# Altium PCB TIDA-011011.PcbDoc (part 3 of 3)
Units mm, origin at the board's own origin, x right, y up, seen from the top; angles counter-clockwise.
Board outline 61 x 47.5 mm, 4 copper layers (Top Layer, Layer 1, Layer 2, Bottom Layer), stack 1.787 mm thick; 171 components, 73 nets, 455 pads, 298 vias.
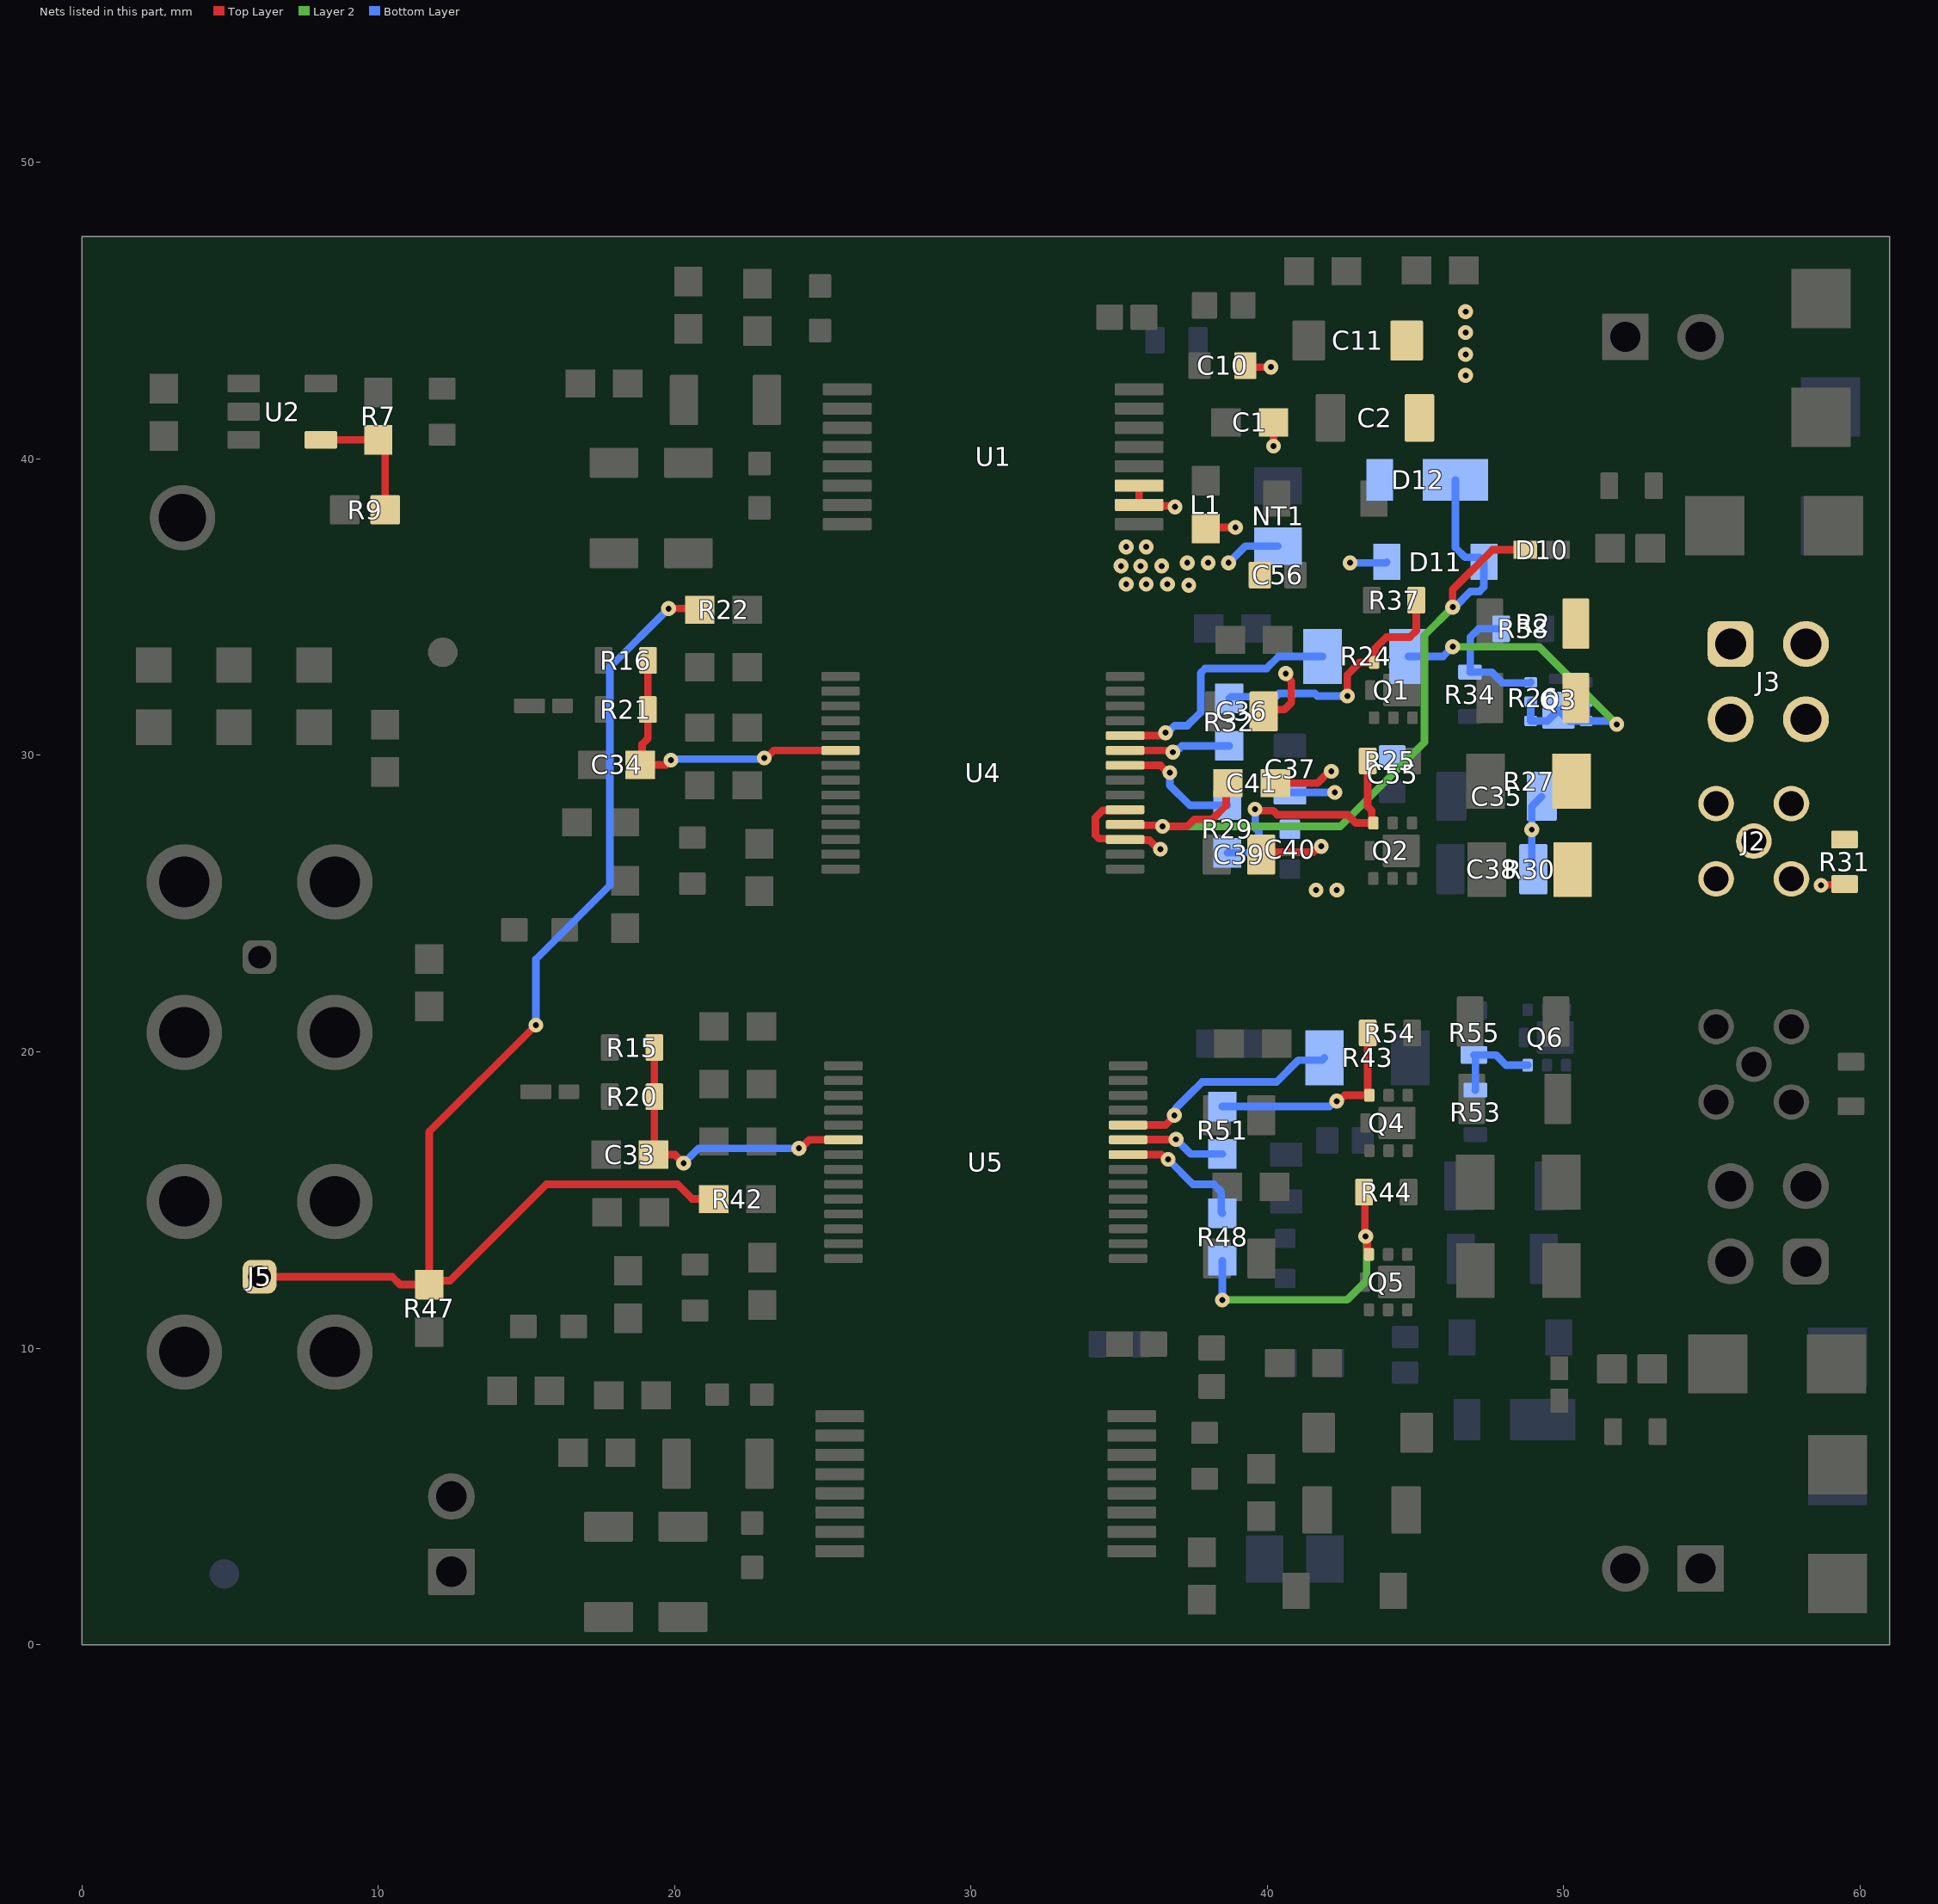
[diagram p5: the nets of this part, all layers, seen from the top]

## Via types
v1: diameter 0.5, hole 0.2, Top Layer to Bottom Layer, tented both sides, 298 vias

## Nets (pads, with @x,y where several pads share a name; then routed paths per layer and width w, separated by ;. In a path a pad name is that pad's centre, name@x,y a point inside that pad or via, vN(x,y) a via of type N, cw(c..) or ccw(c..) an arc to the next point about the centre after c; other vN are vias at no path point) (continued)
NetQ1_3: Q1.3 R32.2 R37.2 | length 9
  Top Layer w0.254: v1(42.698,32.002) 42.698,32.715 43.119,33.136 Q1.3@43.6,33.136 43.632,33.169 43.632,33.603 44.017,33.987 44.809,33.987 45.025,34.203 R37.2@45.025,35.235
  Bottom Layer w0.254: R32.2@38.712,31.921 38.769,31.978 40.289,31.978 40.397,32.086 41.607,32.086 41.691,32.002 v1(42.698,32.002)
NetQ2_3: Q2.3 R25.1 R29.2 | length 8.8
  Top Layer w0.254: v1(39.58,28.183) 39.627,28.136 40.198,28.136 40.338,27.996 42.708,27.996 42.986,27.718 43.521,27.718 43.525,27.722 43.525,28.135 43.388,28.272 R25.1@43.388,29.816
  Bottom Layer w0.254: R29.2@38.649,26.716 39.567,26.716 39.716,26.864 39.716,27.425 39.589,27.552 39.589,28.175 v1(39.58,28.183)
NetQ3_3: Q3.3 R34.2 R38.2 | length 4.5
  Bottom Layer w0.254: R38.2@47.887,34.272 47.129,34.272 46.845,33.987 46.845,32.818 R34.2@46.837,32.809 47.575,32.809 47.94,32.444 48.866,32.444 Q3.3@48.885,32.463
NetQ4_3: Q4.3 R51.2 R54.2 | length 7.2
  Top Layer w0.254: v1(42.342,18.338) 42.408,18.338 42.607,18.536 Q4.3@43.439,18.536 43.439,18.576 43.388,18.628 R54.2@43.388,20.634
  Bottom Layer w0.254: R51.2@38.484,18.156 42.094,18.156 42.275,18.338 v1(42.342,18.338)
NetQ5_3: Q5.3 R44.1 R48.2 | length 10.1
  Top Layer w0.254: R44.1@43.264,15.268 43.291,15.241 43.291,13.806 v1(43.318,13.778) 43.318,13.713 43.376,13.655 43.376,13.217 Q5.3@43.424,13.169
  Layer 2 w0.254: v1(38.484,11.633) 42.697,11.633 43.352,12.288 43.352,13.744 v1(43.318,13.778)
  Bottom Layer w0.254: v1(38.484,11.633) R48.2@38.484,12.951
NetQ6_3: Q6.3 R53.2 R55.2 | length 3.2
  Bottom Layer w0.254: R53.2@47.011,18.7 R53.2@47.022,18.711 47.022,19.844 R55.2@46.972,19.894 47.714,19.894 48.059,19.548 Q6.3@48.78,19.548
NetR7_1: R7.1 R9.2 U2.4 | length 4.6
  Top Layer w0.254: U2.4@8.063,40.643 10.164,40.643 R7.1@10.234,40.712 ; R9.2@10.234,38.284 R7.1@10.234,40.712 ; R7.1@10.247,40.725 R7.1@10.234,40.712
NetR24_1: R24.1 U4.24 | length 8.5
  Top Layer w0.254: U4.24@35.2,30.666 36.401,30.666 36.498,30.763 v1(36.564,30.763)
  Bottom Layer w0.254: v1(36.564,30.763) 36.631,30.763 36.872,31.003 37.303,31.003 37.752,31.453 37.752,32.781 37.901,32.929 39.973,32.929 40.382,33.338 R24.1@41.864,33.338
NetR43_1: R43.1 U5.24 | length 7.7
  Top Layer w0.254: U5.24@35.3,17.532 36.564,17.532 36.863,17.83 v1(36.863,17.86)
  Bottom Layer w0.254: v1(36.863,17.86) 36.91,17.907 36.91,18.094 37.354,18.539 37.798,18.983 40.307,18.983 41.043,19.718 41.844,19.718 R43.1@41.925,19.799
OUTN_BOT: R51.1 U5.23 | length 3.4
  Top Layer w0.254: U5.23@35.3,17.032 35.308,17.04 36.91,17.04 v1(36.918,17.049)
  Bottom Layer w0.254: v1(36.918,17.049) 37.411,16.556 R51.1@38.484,16.556
OUTN_TOP: R32.1 U4.23 | length 3.6
  Top Layer w0.254: U4.23@35.2,30.166 36.687,30.166 36.745,30.108 v1(36.811,30.108)
  Bottom Layer w0.254: v1(36.811,30.108) 36.876,30.108 37.001,30.233 37.031,30.233 37.119,30.321 R32.1@38.712,30.321
OUTP_BOT: R48.1 U5.22 | length 4.4
  Top Layer w0.254: U5.22@35.3,16.532 36.425,16.532 36.584,16.373 v1(36.651,16.373)
  Bottom Layer w0.254: v1(36.651,16.373) 37.491,15.532 38.191,15.532 38.448,15.274 38.448,14.587 R48.1@38.484,14.551
OUTP_TOP: R29.1 U4.22 | length 4.3
  Top Layer w0.254: U4.22@35.2,29.666 36.392,29.666 36.643,29.415 v1(36.71,29.415)
  Bottom Layer w0.254: v1(36.71,29.415) 36.707,29.413 36.707,28.995 37.387,28.316 R29.1@38.649,28.316
RDY_BOT: C33.1 R15.1 R20.2 U5.6 | length 10.5
  Top Layer w0.254: C33.1@19.295,16.532 19.319,16.556 R20.2@19.319,18.486 R15.1@19.319,20.144 ; C33.1@19.296,16.531 20.019,16.531 v1(20.306,16.244) ; v1(24.196,16.746) 24.262,16.746 24.548,17.032 U5.6@25.7,17.032
  Bottom Layer w0.254: v1(20.306,16.244) 20.808,16.746 v1(24.196,16.746)
RDY_TOP: C34.1 R16.1 R21.2 U4.6 | length 10.6
  Top Layer w0.254: C34.1@18.845,29.683 18.908,29.746 18.908,30.374 19.104,30.569 R16.1@19.104,33.204 ; C34.1@18.846,29.682 19.717,29.682 v1(19.876,29.841) ; v1(23.027,29.915) 23.094,29.915 23.344,30.166 U4.6@25.6,30.166
  Bottom Layer w0.254: v1(19.876,29.841) 19.913,29.878 22.99,29.878 v1(23.027,29.915)
TOP-PWM: J5.1 R22.1 R42.1 R47.2 | length 44.3
  Top Layer w0.254: J5.1@6,12.415 10.474,12.415 10.741,12.148 R47.2@11.721,12.148 ; v1(15.321,20.901) 11.721,17.3 R47.2@11.721,12.148 ; v1(19.797,34.951) 20.813,34.951 R22.1@20.85,34.915 ; R42.1@21.325,15.032 21.315,15.041 20.592,15.041 20.102,15.532 15.679,15.532 12.428,12.281 11.853,12.281 R47.2@11.721,12.148
  Bottom Layer w0.254: v1(15.321,20.901) 15.321,23.121 17.819,25.619 17.819,32.974 v1(19.797,34.951)
TOP_Gate: J2.1 J3.2 J3.4 Q3.1 Q3.2 Q3.5 Q3.6 Q3.7 R2.2 R24.2 R26.2 R27.2 R30.2 R31.2 | length 13.2
  Top Layer w0.254: J3.2@55.83,30.867 J3.2@55.83,31.217 ; J2.1@56.411,27.106 J2.1@56.438,27.133 ; R31.2@59.445,27.133 R31.2@59.472,27.159
  Layer 2 w0.254: v1(46.253,33.666) 49.169,33.666 v1(51.787,31.048)
  Bottom Layer w0.254: R24.2@44.764,33.338 45.926,33.338 v1(46.253,33.666) ; Q3.2@48.885,31.813 Q3.1@48.885,31.163 49.455,31.163 Q3.7@49.82,31.528 50.185,31.163 Q3.6@50.755,31.163 ; Q3.5@50.755,31.813 Q3.6@50.755,31.163 ; v1(51.787,31.048) 51.72,31.048 51.605,31.163 Q3.6@50.755,31.163
TOP_OC: C41.1 D10.1 D11.1 D12.1 U4.18 | length 28.7
  Top Layer w0.254: U4.18@35.2,27.666 35.223,27.643 36.425,27.643 v1(36.462,27.606) 37.301,27.606 37.541,27.845 38.142,27.845 38.612,28.316 38.612,29.009 C41.1@38.669,29.066 ; v1(46.253,35) 46.253,35.592 47.597,36.935 D10.1@48.709,36.935
  Layer 2 w0.254: v1(36.462,27.606) 42.466,27.606 45.3,30.44 45.3,34.047 v1(46.253,35)
  Bottom Layer w0.254: v1(46.253,35) 46.32,35 46.849,35.529 47.155,35.529 47.304,35.678 D11.1@47.304,36.524 47.146,36.681 46.672,36.681 46.347,37.006 D12.1@46.347,39.293
TOP_Source: C1.2 C2.1 C10.2 C11.2 C35.1 C36.1 C37.1 C38.2 C39.2 C40.2 C41.2 C55.1 C56.2 D11.2 D12.2 J2.2 J2.3 J2.4 J2.5 J3.1 J3.3 L1.1 NT1.2 R31.1 U1.10 U1.11 U4.17 U4.19 | length 23.3
  Top Layer w0.254: U4.19@35.2,28.166 35.177,28.143 34.444,28.143 34.2,27.899 34.2,27.315 34.326,27.189 35.177,27.189 U4.17@35.2,27.166 35.223,27.143 36.017,27.143 36.321,26.839 v1(36.387,26.839) ; U1.11@35.675,39.099 U1.10@35.675,38.449 35.709,38.415 36.854,38.415 v1(36.888,38.381) ; L1.1@37.924,37.659 37.957,37.692 v1(38.923,37.692) ; C10.2@39.259,43.146 39.307,43.097 v1(40.118,43.097) ; C39.2@39.79,26.653 39.872,26.735 41.551,26.735 41.748,26.932 v1(41.814,26.932) ; C36.1@39.873,31.481 39.94,31.548 40.581,31.548 40.812,31.779 40.812,32.504 40.621,32.695 v1(40.621,32.761) ; v1(40.208,40.431) C1.2@40.208,41.231 ; C41.2@40.269,29.066 41.693,29.066 42.092,29.465 v1(42.158,29.465) ; J2.4@57.681,25.836 J2.4@57.77,25.748 ; v1(58.676,25.614) 58.698,25.637 59.449,25.637 R31.1@59.472,25.659
  Bottom Layer w0.254: v1(38.692,36.494) 39.255,37.057 NT1.2@40.362,37.057 ; C37.1@40.762,28.751 v1(42.275,28.751) ; v1(42.789,36.494) 44,36.494 D11.2@44.029,36.524 ; C38.2@48.973,26.158 48.92,26.212 v1(48.92,27.497) 48.922,27.5 48.922,28.283 C35.1@49.256,28.616 ; J3.1@55.749,33.676 J3.1@55.83,33.757
  other v1: 41.64,25.461 42.345,25.461 37.353,35.739 35.236,35.771 35.913,35.771 36.628,35.771 35.064,36.389 35.721,36.38 36.432,36.389 37.299,36.494 38.004,36.494 35.236,37.033 35.913,37.033 46.689,42.816 46.689,43.521 46.689,44.262 46.689,44.967
pads on no net: FID1.33 FID2.1 LBL1.0 U4.2 U4.3 U4.9 U4.12 U4.13 U4.16 U4.27 U5.2 U5.3 U5.9 U5.12 U5.13 U5.16 U5.27

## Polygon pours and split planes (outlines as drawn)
BOT_Source on Top Layer "TOP_LAYER_BOT_SOURCE_P028" (solid, pour order 28): 48.081,9.655 49.162,10.736 50.722,10.736 51.703,11.722 59.312,11.722 60.374,12.785 60.374,22.581 34.681,22.581 34.2,22.1 34.2,0.8 34.3,0.7 47.312,0.7 48.081,1.469
BOT_Gate on Top Layer "TOP_LAYER_BOT_GATE_P003" (solid, pour order 3): 49.035,21.79 49.035,11.443 49.01,11.418 49.042,11.385 50.797,11.385 50.797,13.664 51.159,14.026 59.212,14.026 59.212,16.473 58.477,17.207 56.8,17.207 56.647,17.361 56.647,18.214 57.654,19.221 60.042,19.221 60.226,19.405 60.226,20.605 50.431,20.605 50.431,21.908 49.035,21.908
TOP_Source on Top Layer "TOP_LAYER_TOP_SOURCE_P033" (solid, pour order 33): 34,46.841 47.853,46.841 48.318,46.376 48.318,37.797 51.152,34.964 59.454,34.964 60.374,34.044 60.374,25.19 60.274,25.089 34,25.089 34,46.798
GND on Top Layer "TOP_LAYER_GND_P025" (solid, pour order 25): 27.024,8.666 25.997,9.693 25.997,11.749 27.024,12.775 27.024,20.132 25.809,21.347 25.809,24.631 27.024,25.847 27.024,33.266 25.997,34.293 25.997,35.281 27.024,36.308 27.024,46.994 1.894,46.994 1,46.1 1,1.106 1.139,0.967 27,0.967 27.024,0.991
NetD13_2 on Top Layer "TOP_LAYER_NETD13_2_P034" (solid, pour order 34): 57.359,7.309 57.407,7.357 58.284,8.234 60.222,8.234 60.374,8.387 60.374,10.736 57.977,10.736 57.977,9.114 56.852,7.99 56.537,7.99 56.537,7.309
TOP_Gate on Top Layer "TOP_LAYER_TOP_GATE_P000" (solid, remove dead copper, pour order 0): 49.585,35.318 49.585,24.939 51.105,24.939 52.278,26.113 52.278,26.484 60.182,26.484 60.182,26.632 60.182,27.882 60.063,28.001 54.616,28.001 54,28.616 54,29.597 59.758,29.597 60.138,29.977 60.138,32.184 59.775,32.547 51.905,32.547 51.029,33.423 51.029,35.475 49.742,35.475
NetD19_2 on Top Layer "TOP_LAYER_NETD19_2_P031" (solid, pour order 31): 52.714,6.683 52.714,8.347 52.5,8.561 52.5,10.518 52.571,10.589 56.299,10.589 56.299,8.428 56.278,8.407 54.142,8.407 53.577,7.842 53.577,6.683
NetD13_1 on Top Layer "TOP_LAYER_NETD13_1_P024" (solid, pour order 24): 57.752,6.861 57.752,6.163 57.657,6.067 57.099,6.067 57.099,4.993 57.339,4.753 60.527,4.753 60.527,7.185 58.352,7.185 58.352,7.189 58.08,7.189
NetD14_1 on Top Layer "TOP_LAYER_NETD14_1_P021" (solid, pour order 21): 50.832,0.7 60.222,0.7 60.527,1.006 60.527,3.404 56.537,3.404 55.888,4.053 51.173,4.053 50.832,3.713
NetD8_2 on Top Layer "TOP_LAYER_NETD8_2_P011" (solid, pour order 11): 57.514,35.85 60.014,35.85 60.486,36.321 60.486,39.235 57.723,39.235 57.514,39.026
NetD18_2 on Top Layer "TOP_LAYER_NETD18_2_P016" (solid, pour order 16): 52.5,39.749 52.5,36.255 56.411,36.255 56.411,39.003 56.179,39.235 53.983,39.235 53.469,39.749
NetD8_1 on Top Layer "TOP_LAYER_NETD8_1_P007" (solid, pour order 7): 56.647,40.184 57.425,40.184 60.486,40.184 60.486,42.813 57.626,42.813 56.997,42.184 56.796,41.982 56.647,41.982
NetD9_1 on Top Layer "TOP_LAYER_NETD9_1_P004" (solid, pour order 4): 50.683,42.898 55.6,42.898 56.549,43.847 59.605,43.847 60.575,43.847 60.574,47.257 57.425,47.257 56.172,46.004 51.169,46.004 50.683,45.519
BOT_Source on Bottom Layer "BOTTOM_LAYER_BOT_SOURCE_P022" (solid, pour order 22): 34.2,0.8 34.3,0.7 47.32,0.7 48.081,1.461 48.081,6.069 53.735,11.722 59.312,11.722 60.374,12.785 60.374,22.581 34.681,22.581 34.2,22.1 34.2,20.498
TOP_Source on Bottom Layer "BOTTOM_LAYER_TOP_SOURCE_P030" (solid, pour order 30): 34,46.841 47.853,46.841 48.318,46.376 48.318,37.797 51.152,34.964 59.454,34.964 60.527,33.891 60.527,25.343 60.274,25.089 34,25.089 34,46.798
GND on Bottom Layer "BOTTOM_LAYER_GND_P010" (solid, pour order 10): 27.024,12.773 27.021,12.773 25.997,11.748 25.997,9.693 27.024,8.666 27.024,0.991 27,0.967 2.151,0.967 1,2.118 1,46.1 1.894,46.994 27.024,46.994 27.024,36.308 25.997,35.281 25.997,34.293 27.024,33.266 27.024,25.847 25.809,24.631 25.809,21.347 27.024,20.132
NetD13_1 on Bottom Layer "BOTTOM_LAYER_NETD13_1_P017" (solid, pour order 17): 57.752,6.163 57.752,6.546 58.067,6.861 60.374,6.861 60.374,4.457 58.049,4.457 57.752,4.753 57.339,4.753 57.099,4.993 57.099,6.067 57.657,6.067
NetD13_2 on Bottom Layer "BOTTOM_LAYER_NETD13_2_P018" (solid, pour order 18): 57.359,7.309 57.407,7.357 58.284,8.234 60.222,8.234 60.374,8.387 60.374,10.961 57.977,10.961 57.977,9.114 56.852,7.99 56.537,7.99 56.537,7.309
NetD8_2 on Bottom Layer "BOTTOM_LAYER_NETD8_2_P009" (solid, pour order 9): 60.014,35.85 60.35,36.188 60.353,39.235 57.723,39.235 57.514,39.026 57.514,35.85
NetD8_1 on Bottom Layer "BOTTOM_LAYER_NETD8_1_P008" (solid, pour order 8): 56.65,40.184 57.425,40.184 60.353,40.184 60.353,42.813 57.626,42.813 56.796,41.982 56.65,41.982
BOT_Source on Layer 1 "LAYER_1_BOT_SOURCE_P019" (solid, pour order 19): 34.2,0.8 34.3,0.7 47.312,0.7 48.081,1.469 48.081,11.355 48.449,11.722 59.312,11.722 60.374,12.785 60.374,22.581 34.681,22.581 34.2,22.1 34.2,20.498
TOP_Source on Layer 1 "LAYER_1_TOP_SOURCE_P032" (solid, pour order 32): 34,46.841 47.853,46.841 48.318,46.376 48.318,37.797 51.115,35 59.418,35 60.527,33.891 60.527,25.343 60.274,25.089 34,25.089 34,46.798
GND on Layer 1 "LAYER_1_GND_P020" (solid, pour order 20): 27.024,8.666 25.997,9.693 25.997,11.746 27.024,12.773 27.024,20.132 25.809,21.347 25.809,24.638 27.024,25.839 27.024,33.266 25.997,34.293 25.997,35.281 27.024,36.308 27.024,46.994 1.894,46.994 1,46.1 1,1.106 1.139,0.967 27,0.967 27.024,0.991
BOT_Source on Layer 2 "LAYER_2_BOT_SOURCE_P037" (solid, pour order 37): 34.2,22.1 34.2,0.8 34.3,0.7 47.32,0.7 48.081,1.461 48.081,9.655 49.162,10.736 50.722,10.736 50.722,10.741 51.703,11.722 59.312,11.722 60.353,12.763 60.353,22.581 34.681,22.581
TOP_Source on Layer 2 "LAYER_2_TOP_SOURCE_P036" (solid, pour order 36): 34,25.089 60.274,25.089 60.401,25.216 60.401,34.018 59.454,34.964 51.152,34.964 48.318,37.797 48.318,46.376 47.853,46.841 34.022,46.841 34,46.819
GND on Layer 2 "LAYER_2_GND_P035" (solid, pour order 35): 1,46.1 1.753,46.853 27.024,46.853 27.024,36.308 25.997,35.281 25.997,34.293 27.024,33.266 27.024,25.847 27.017,25.847 25.809,24.638 25.809,21.347 27.024,20.132 27.024,12.775 27.023,12.775 25.997,11.749 25.997,9.693 27.024,8.666 27,8.642 27,0.967 1.139,0.967 1,1.106

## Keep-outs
Keep-Out Layer:
  lines w1.5: 30.663,12.127 30.663,19.747 ; 30.663,25.188 30.663,32.808 ; 30.7,1.666 30.7,9.286 ; 30.7,36.2 30.7,43.82
  text ".Layer_Name" at 14.656,-21.806 h1.52

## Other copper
Top Layer:
  text ".Layer_Name" at 14.656,-21.806 h1.52
Bottom Layer:
  text ".Layer_Name" at 14.656,-21.806 h1.52

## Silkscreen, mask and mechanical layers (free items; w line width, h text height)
Top Overlay:
  lines w0.254: 9.477,33.162 10.477,33.162 ; 9.48,33.751 10.48,33.751 ; 9.486,33.148 9.98,33.641 ; 9.986,33.641 10.48,33.148
  text "18V" at 40.587,42.289 h0.5
  text "GND" at 5.383,36.5 h1
  text "TOP" at 22.361,36.007 h1
  text "G" at 60.205,30.927 h0.5
  text "-5V" at 37.764,24.372 h0.5
  text "BOT" at 4.747,17.575 h1
  text "G" at 59.805,15.333 h0.5
  text "BOT" at 26.919,9.761 h1
  text "-5V" at 36.399,7.59 h0.5
  text "TOP" at 4.747,6.79 h1
  text "GND" at 0.17,5.793 h1
  text "18V" at 39.631,1.862 h0.5 r90
  text "12V" at 0.2,1.018 h1
  text ".Layer_Name" at 14.656,-21.806 h1.52
Bottom Overlay:
  text "Danger High Voltage" at 50.905,44.844 h2
  text "'.PRJ_Number'.PCB_Rev" at 18.485,28.033 h2.75
  text ".Layer_Name" at 14.656,-21.806 h1.52
Top Paste:
  text ".Layer_Name" at 14.656,-21.806 h1.52
Bottom Paste:
  text ".Layer_Name" at 14.656,-21.806 h1.52
Top Solder:
  text ".Layer_Name" at 14.656,-21.806 h1.52
  text ".Layer_Name" at 14.656,-21.806 h1.52
Bottom Solder:
  text ".Layer_Name" at 14.656,-21.806 h1.52
Drill Guide:
  text ".Layer_Name" at 14.656,-21.806 h1.52
M1 Board Outline:
  lines w0.5: 0,0 0,47.5 61,47.5 61,0 0,0
  lines w1.5: 30.663,12.127 30.663,19.747 ; 30.663,25.188 30.663,32.808 ; 30.7,1.666 30.7,9.286 ; 30.7,36.2 30.7,43.82
  text ".Layer_Name" at 14.656,-21.806 h1.52
M2 Board Dimensions:
  rectangle: 3.175,-10.16 12.7,-6.985
  rectangle: 0,-6.985 3.175,-3.81
  lines w0.178: 0,-6.985 25.4,-6.985 ; 3.175,-10.16 3.175,-3.81 ; 6.35,-10.16 6.35,-3.81 ; 12.7,-10.16 12.7,-3.81 ; 19.05,-10.16 19.05,-3.81 ; 0,-10.16 0,-3.81 25.4,-3.81 25.4,-10.16 0,-10.16
  text ".Layer_Name" at 14.656,-21.806 h1.52
M3 3D STEP Top:
  text ".Layer_Name" at 14.656,-21.806 h1.52
M4 3D STEP Bottom:
  text ".Layer_Name" at 14.656,-21.806 h1.52
M5 Assembly Top:
  lines w0.254: -7.417,-23.626 160.223,-23.626 ; -7.417,-18.462 160.274,-18.462 ; -7.417,-13.297 -7.417,-28.791 94.31,-28.791 160.274,-28.791 160.274,-13.297 -7.404,-13.297 -7.404,-28.791 32.614,-28.791 ; 55.194,-28.791 55.194,-13.297 ; 87.376,-18.462 87.376,-13.297 ; 108.712,-18.462 108.712,-13.297 ; 124.511,-28.956 124.511,-23.804
  text "COMPONENTS MARKED 'DNP' SHOULD NOT BE POPULATED." at 29.299,-8.09 h1.52
  text "ASSEMBLY VARIANT:" at 29.286,-11.024 h1.52
  text ".VariantName" at 55.601,-11.024 h1.52
  text "PCB VIEWED FROM TOP SIDE" at -5.804,-16.654 h1.52
  text "BOARD #:" at 57.099,-16.654 h1.52
  text ".PRJ_Number" at 70.955,-16.654 h1.52
  text "REV:" at 92.405,-16.654 h1.52
  text ".PCB_Rev" at 99.809,-16.654 h1.52
  text "SVN REV:" at 113.69,-16.654 h1.52
  text ".VersionControl_RevNumber" at 126.543,-16.654 h1.52
  text "PLOT NAME =" at -5.804,-27.034 h1.52
  text ".plot_File_Name" at 14.656,-27.034 h1.52
  text "GENERATED    :" at 57.15,-27.034 h1.52
  text ".Print_Date" at 79.235,-27.034 h1.52
  text ".Print_Time" at 97.752,-27.034 h1.52
  text "TEXAS INSTRUMENTS" at 129.87,-27.034 h1.52
M6 Assembly Bottom:
  lines w0.254: -7.429,-18.474 160.261,-18.474 ; -7.379,-23.639 160.261,-23.639 ; 28.334,-28.969 28.334,-23.817 ; 44.133,-18.474 44.133,-13.31 ; 65.468,-18.474 65.468,-13.31 ; 97.65,-28.804 97.65,-13.31 ; 120.231,-28.804 160.249,-28.804 160.249,-13.31 -7.429,-13.31 -7.429,-28.804 58.534,-28.804 160.261,-28.804 160.261,-13.31
  text "COMPONENTS MARKED 'DNP' SHOULD NOT BE POPULATED." at 154.991,-8.077 h1.52
  text ".VariantName" at 128.473,-11.024 h1.52
  text "ASSEMBLY VARIANT:" at 154.864,-11.024 h1.52
  text ".VersionControl_RevNumber" at 26.302,-16.667 h1.52
  text "SVN REV:" at 39.154,-16.667 h1.52
  text ".PCB_Rev" at 53.035,-16.667 h1.52
  text "REV:" at 60.439,-16.667 h1.52
  text ".PRJ_Number" at 81.89,-16.667 h1.52
  text "BOARD #:" at 95.745,-16.667 h1.52
  text "PCB VIEWED FROM BOTTOM SIDE" at 158.648,-16.667 h1.52
  text "TEXAS INSTRUMENTS" at 22.974,-27.047 h1.52
  text ".Print_Time" at 55.093,-27.047 h1.52
  text ".Print_Date" at 73.609,-27.047 h1.52
  text "GENERATED    :" at 95.694,-27.047 h1.52
  text ".plot_File_Name" at 138.189,-27.047 h1.52
  text "PLOT NAME =" at 158.648,-27.047 h1.52
M9 Title Sheet:
  drawing of 56 lines, arcs and shapes, not listed
  text "1" at 26.882,339.887 h1.78
  text "2" at 111.354,339.887 h1.78
  text "3" at 195.936,339.887 h1.78
  text "4" at 280.645,339.887 h1.78
  text "5" at 365.1,339.887 h1.78
  text "6" at 449.809,339.887 h1.78
  text "A" at -11.76,294.726 h1.78
  text "A" at 488.62,294.726 h1.78
  text "B" at -11.76,199.476 h1.78
  text "B" at 488.62,199.476 h1.78
  text "C" at -11.76,104.226 h1.78
  text "C" at 488.62,104.226 h1.78
  text "D" at -11.76,8.976 h1.78
  text "D" at 488.62,8.976 h1.78
  text "PROJECT TITLE:" at 410.032,6.817 h1.14
  text ".PRJ_Title" at 411.302,3.431 h1.78
  text "DESIGNED FOR:" at 410.032,-0.828 h1.14
  text ".PRJ_Customer" at 411.302,-4.384 h1.78
  text "FILE NAME:" at 410.032,-8.448 h1.14
  text ".PCB_File_Name_No_Path" at 411.302,-11.496 h1.78
  text "Texas Instruments (TI) and/or its licensors do not warrant the accuracy or completeness of this specification" at 283.807,-15.607 h1.14
  text "ENGINEER:" at 410.032,-15.814 h1.14
  text "LAYOUT BY:" at 448.259,-15.814 h1.14
  text "or any information contained therein. TI and/or its licensors do not warrant that this design will meet" at 282.664,-18.469 h1.14
  text ".PRJ_Engineer" at 411.302,-19.751 h1.78
  text ".PCB_Layout" at 449.542,-19.751 h1.78
  text "the specifications, will be suitable for your application or fit for any particular purpose, or will operate in" at 282.664,-21.33 h1.14
  text ".Layer_Name" at 14.656,-21.806 h1.52
  text "ALTIUM DESIGNER VERSION:" at 448.259,-23.688 h1.14
  text "an implementation. TI and/or its licensors do not warrant that the design is production worthy. You should" at 282.664,-24.192 h1.14
  text "completely validate and test your design implementation to confirm the system functionality for your application." at 283.807,-27.054 h1.14
  text ".print_Scale" at 411.302,-27.075 h1.78
  text ".Application_BuildNumber" at 449.542,-27.075 h1.78
  text "1" at 26.882,-33.493 h1.78
  text "2" at 111.354,-33.493 h1.78
  text "3" at 195.936,-33.493 h1.78
  text "4" at 280.645,-33.493 h1.78
  text "5" at 365.1,-33.493 h1.78
  text "6" at 449.809,-33.493 h1.78
M10 Fab Notes:
  drawing of 189 lines, arcs and shapes, not listed
  text "DESIGN INFORMATION" at 436.322,161.675 h1.52
  text "MIN. TRACK WIDTH:" at 419.95,158.319 h1.52
  text "8" at 447.794,158.32 h1.52
  text "MIL" at 451.725,158.319 h1.52
  text "MIN. CLEARANCE:" at 419.95,155.167 h1.52
  text "MIL" at 451.725,155.167 h1.52
  text "7.874" at 443.475,155.05 h1.52
  text "MIN. VIA PAD SIZE:" at 419.95,152.014 h1.52
  text "24" at 447.033,152.014 h1.52
  text "MIL" at 451.725,152.014 h1.52
  text "0.05mm (2MIL)" at 437.603,148.714 h1.52
  text "MINIMUM ANNULAR RING" at 411.587,148.506 h1.52
  text "EXTERNAL" at 455.586,148.506 h1.52
  text "PER" at 416.667,145.708 h1.52
  text "IPC-D-275 CLASS 2 LEVEL C" at 422.255,145.708 h1.52
  text "MIL, HOLES" at 460.056,143.156 h1.52
  text "+/-" at 450.088,142.938 h1.52
  text "+/-" at 471.78,142.938 h1.52
  text "REGISTRATION TOLERANCES:" at 411.587,142.911 h1.52
  text "METAL" at 442.062,142.911 h1.52
  text "5" at 456.697,142.911 h1.52
  text "3" at 477.855,142.911 h1.52
  text "MIL" at 480.808,142.911 h1.52
  text "HOLE SIZE TOLERANCE (UNLESS OTHERWISE SPECIFIED):" at 411.587,140.414 h1.52
  text "+/-" at 471.78,140.341 h1.52
  text "3" at 477.855,140.314 h1.52
  text "MIL" at 480.808,140.314 h1.52
  text "MATERIAL:" at 409.688,136.818 h1.52
  text "FR-4 High Tg" at 434.744,133.553 h1.52
  text "X" at 431.075,133.35 h1.52
  text "FR-4" at 420.382,133.235 h1.52
  text "OTHER" at 458.177,133.235 h1.52
  text "62 MIL (1.6mm) +/-10%" at 428.512,129.602 h1.52
  text "X" at 425.462,129.54 h1.52
  text "THICKNESS:" at 411.587,129.394 h1.52
  text "OTHER" at 461.149,129.394 h1.52
  text "TOLERANCE:" at 411.587,125.88 h1.52
  text "X" at 433.133,125.88 h1.52
  text "ANSI IPC-6012 TYPE 3 CLASS 2" at 437.654,125.88 h1.52
  text "OTHER +/-" at 437.654,122.218 h1.52
  text "BOW & TWIST:" at 411.587,118.53 h1.52
  text "X" at 433.133,118.53 h1.52
  text "ANSI IPC-6012 TYPE 3 CLASS 2" at 437.654,118.53 h1.52
  text "OTHER +/-" at 437.654,114.804 h1.52
  text "DRILLING:" at 409.688,111.486 h1.52
  text "NC_DRILL FILES" at 454.418,108.815 h1.52
  text "REFERENCE:" at 411.587,108.715 h1.52
  text "X" at 428.281,108.712 h1.52
  text "AS SHOWN" at 432.802,108.715 h1.52
  text "X" at 451.167,108.715 h1.52
  text "OTHER" at 461.987,105.101 h1.52
  text "PTH COPPER THICKNESS:" at 411.579,105.012 h1.52
  text "X" at 440.516,105.012 h1.52
  text "20-30 um" at 443.767,105.012 h1.52
  text "BOARD FINISH:" at 409.688,101.263 h1.52
  text "SILKSCREEN:" at 413.631,98.466 h1.52
  text "X" at 437.959,98.466 h1.52
  text "TOP" at 440.93,98.466 h1.52
  text "X" at 450.913,98.466 h1.52
  text "BOTTOM" at 453.91,98.466 h1.52
  text "SILKSCREEN COLOR:" at 413.631,94.524 h1.52
  text "X" at 437.933,94.524 h1.52
  text "WHITE" at 440.93,94.524 h1.52
  text "OTHER" at 453.91,94.524 h1.52
  text "X" at 441.261,90.88 h1.52
  text "GREEN" at 444.258,90.88 h1.52
  text "OTHER" at 459.955,90.88 h1.52
  text "SOLDER RESIST COLOR:" at 413.631,90.706 h1.52
  text "X" at 441.261,86.962 h1.52
  text "MATTE" at 444.258,86.962 h1.52
  text "SEMI-GLOSS" at 459.943,86.946 h1.52
  text "IMMERSION GOLD (ENIG)" at 436.638,82.574 h1.52
  text "ENEPIG" at 470.611,82.39 h1.52
  text "SURFACE FINISH:" at 409.688,82.365 h1.52
  text "X" at 432.117,82.365 h1.52
  text "IMM. TIN/SILVER OR EQUIV" at 418.059,78.877 h1.52
  text "OTHER" at 454.418,78.777 h1.52
  text "ARRAY/PANEL:" at 409.688,74.831 h1.52
  text "CUT AND TRIM PER M1 BOARD OUTLINE" at 436.638,74.622 h1.52
  text "N.C. ROUTE" at 436.638,71.168 h1.52
  text "X" at 454.113,71.168 h1.52
  text "V. SCORE" at 458.634,71.168 h1.52
  text "CERTIFICATION:" at 409.688,67.888 h1.52
  text "MATERIALS AND WORKMANSHIP FOR ALL PCBS" at 428.103,67.888 h1.52
  text "TO MEET OR EXCEED THE REQUIREMENTS OF:" at 428.103,65.499 h1.52
  text "X" at 418.896,62.232 h1.52
  text "ANSI IPC-A-600F CLASS ->" at 422.147,62.232 h1.52
  text "X" at 464.006,62.232 h1.52
  text "2" at 466.8,62.232 h1.52
  text "1" at 458.799,62.194 h1.52
  text "3" at 475.792,62.194 h1.52
  text "X" at 439.521,58.481 h1.52
  text "RoHS" at 442.772,58.481 h1.52
  text "OTHER" at 459.14,58.481 h1.52
  text "PER ORDER" at 469.225,58.481 h1.52
  text "ALL BOARDS MUST MEET OR EXCEED UL94-V0 REQUIREMENTS." at 410.388,54.574 h1.52
  text "PCB MUST BEAR THE UL94V-0 UL REGISTERED MATERIAL ID NUMBER" at 410.388,51.626 h1.52
  text "ADDITIONAL REQUIREMENTS:" at 409.688,47.322 h1.52
  text "MICROSECTION:" at 411.587,44.601 h1.52
  text "YES" at 434.593,44.601 h1.52
  text "REQUIRED" at 456.475,40.935 h1.52
  text "BARE BOARD ELEC. TEST:" at 411.587,40.863 h1.52
  text "NONE" at 444.753,40.863 h1.52
  text "X" at 453.478,40.863 h1.52
  text "PER ORDER" at 471.512,40.863 h1.52
  text "XX MIL VIAS REQUIRE NON-CONDUCTIVE FILL AND PLANARIZE" at 415.858,35.657 h1.5
  text "XX MIL VIAS REQUIRE CONDUCTIVE FILL AND PLANARIZE" at 416.062,33.016 h1.52
  text "OUTER XX MIL TRACES REQUIRE 50 OHM SINGLE-ENDED IMPEDANCE" at 416.037,28.866 h1.47
  text "LAYER 2 & 3 (INNER LAYERS) XX MIL WIDE, XX MIL SPACE / TRACES REQUIRE 100 OHM DIFFERENTIAL IMPEDANCE" at 415.833,22.879 h1.52
  text ".Layer_Name" at 14.656,-21.806 h1.52
M11 Gerber Information:
  lines w0.254: -7.417,-23.626 160.223,-23.626 ; -7.417,-18.462 160.274,-18.462 ; -7.417,-13.297 -7.417,-28.791 94.31,-28.791 160.274,-28.791 160.274,-13.297 -7.404,-13.297 -7.404,-28.791 32.614,-28.791 ; 55.194,-28.791 55.194,-13.297 ; 87.376,-18.462 87.376,-13.297 ; 108.712,-18.462 108.712,-13.297 ; 124.511,-28.956 124.511,-23.804
  text "ALL ARTWORK VIEWED FROM TOP SIDE" at -5.804,-16.654 h1.52
  text "BOARD #:" at 57.099,-16.654 h1.52
  text ".PRJ_Number" at 70.955,-16.654 h1.52
  text "REV:" at 92.405,-16.654 h1.52
  text ".PCB_Rev" at 99.809,-16.654 h1.52
  text "SVN REV:" at 113.69,-16.654 h1.52
  text ".VersionControl_RevNumber" at 126.543,-16.654 h1.52
  text "LAYER NAME =" at -5.804,-21.806 h1.52
  text "PLOT NAME =" at -5.804,-27.034 h1.52
  text ".plot_File_Name" at 14.656,-27.034 h1.52
  text "GENERATED    :" at 57.15,-27.034 h1.52
  text ".Print_Date" at 79.235,-27.034 h1.52
  text ".Print_Time" at 97.752,-27.034 h1.52
  text "TEXAS INSTRUMENTS" at 129.87,-27.034 h1.52
M12 Stackup:
  drawing of 295 lines, arcs and shapes, not listed
  text "Layer" at 370.969,332.524 h1.52
  text "Name" at 381.38,332.524 h1.52
  text "Material" at 404.996,332.524 h1.52
  text "Thickness" at 426.834,332.524 h1.52
  text "Constant" at 443.34,332.524 h1.52
  text "Board Layer Stack" at 457.814,332.524 h1.52
  text "Top Overlay" at 381.38,329.476 h1.52
  text "Top Solder" at 381.38,326.428 h1.52
  text "Solder Resist" at 404.996,326.428 h1.52
  text "0,40mil" at 426.834,326.428 h1.52
  text "3.5" at 443.34,326.428 h1.52
  text "1" at 370.969,323.38 h1.52
  text "Top Layer" at 381.38,323.38 h1.52
  text "1,40mil" at 426.834,323.38 h1.52
  text "Dielectric 1" at 381.38,320.332 h1.52
  text "PP-006" at 404.996,320.332 h1.52
  text "2,80mil" at 426.834,320.332 h1.52
  text "4.1" at 443.34,320.332 h1.52
  text "2" at 370.969,317.284 h1.52
  text "Layer 1" at 381.38,317.284 h1.52
  text "CF-004" at 404.996,317.284 h1.52
  text "1,38mil" at 426.834,317.284 h1.52
  text "Dielectric1" at 381.38,314.236 h1.52
  text "FR-4 High Tg" at 404.996,314.236 h1.52
  text "59,20mil" at 426.834,314.236 h1.52
  text "4.8" at 443.34,314.236 h1.52
  text "3" at 370.969,311.188 h1.52
  text "Layer 2" at 381.38,311.188 h1.52
  text "CF-004" at 404.996,311.188 h1.52
  text "1,38mil" at 426.834,311.188 h1.52
  text "Dielectric 2" at 381.38,308.14 h1.52
  text "PP-006" at 404.996,308.14 h1.52
  text "2,80mil" at 426.834,308.14 h1.52
  text "4.1" at 443.34,308.14 h1.52
  text "4" at 370.969,305.092 h1.52
  text "Bottom Layer" at 381.38,305.092 h1.52
  text "1,40mil" at 426.834,305.092 h1.52
  text "Bottom Solder" at 381.38,302.044 h1.52
  text "Solder Resist" at 404.996,302.044 h1.52
  text "0,40mil" at 426.834,302.044 h1.52
  text "3.5" at 443.34,302.044 h1.52
  text "Bottom Overlay" at 381.38,298.996 h1.52
  text ".Layer_Name" at 14.656,-21.806 h1.52
M13 Component Bodies Top:
  text ".Layer_Name" at 14.656,-21.806 h1.52
M14 Component Bodies Bottom:
  text ".Layer_Name" at 14.656,-21.806 h1.52
M15 Courtyards Top:
  text ".Layer_Name" at 14.656,-21.806 h1.52
M16 Courtyards Bottom:
  text ".Layer_Name" at 14.656,-21.806 h1.52
Drill Drawing:
  circle w0.254: c845.521,310.457 r0.702
  lines w0.254: 844.82,300.283 845.521,300.634 846.223,300.283 845.872,300.985 846.223,301.686 845.521,301.335 844.82,301.686 845.17,300.985 844.82,300.283 ; 844.82,304.844 846.223,304.844 845.521,303.44 844.82,304.844 ; 844.82,306.949 845.17,306.949 845.521,306.598 845.872,306.949 846.223,306.949 845.872,307.3 846.223,307.65 845.872,307.65 845.521,308.001 845.17,307.65 844.82,307.65 845.17,307.3 844.82,306.949 ; 844.82,316.071 846.223,316.071 846.223,317.474 844.82,317.474 844.82,316.071
  lines w0.305: 843.547,296.178 925.647,296.178 ; 843.547,318.281 925.647,318.281 ; 852.129,293.021 852.129,321.438 ; 860.565,293.021 860.565,321.438 ; 876.735,293.021 876.735,321.438 ; 883.319,293.021 883.319,321.438 ; 892.85,293.021 892.85,321.438 ; 911.256,293.021 911.256,321.438 ; 843.547,293.021 925.647,293.021 925.647,321.438 843.547,321.438 843.547,293.021
  text "Symbol" at 845.442,319.228 h1.83
  text "Quantity" at 853.076,319.228 h1.83
  text "Finished Hole Size" at 861.512,319.228 h1.83
  text "Plated" at 877.683,319.228 h1.83
  text "Hole Type" at 884.266,319.228 h1.83
  text "Drill Layer Pair" at 893.798,319.228 h1.83
  text "Hole Tolerance" at 912.203,319.228 h1.83
  text "298" at 853.076,316.071 h1.52
  text "7,87mil (0,200mm)" at 861.512,316.071 h1.52
  text "PTH" at 877.683,316.071 h1.52
  text "Round" at 884.266,316.071 h1.52
  text "Top Layer - Bottom Layer" at 893.798,316.071 h1.52
  text "2" at 853.076,312.913 h1.52
  text "29,92mil (0,760mm)" at 861.512,312.913 h1.52
  text "PTH" at 877.683,312.913 h1.52
  text "Round" at 884.266,312.913 h1.52
  text "Top Layer - Bottom Layer" at 893.798,312.913 h1.52
  text "+/-3,94mil" at 912.203,312.913 h1.52
  text "F" at 844.8,312.659 h1.4
  text "10" at 853.076,309.755 h1.52
  text "33,07mil (0,840mm)" at 861.512,309.755 h1.52
  text "PTH" at 877.683,309.755 h1.52
  text "Round" at 884.266,309.755 h1.52
  text "Top Layer - Bottom Layer" at 893.798,309.755 h1.52
  text "6" at 853.076,306.598 h1.52
  text "40,16mil (1,020mm)" at 861.512,306.598 h1.52
  text "PTH" at 877.683,306.598 h1.52
  text "Round" at 884.266,306.598 h1.52
  text "Top Layer - Bottom Layer" at 893.798,306.598 h1.52
  text "8" at 853.076,303.44 h1.52
  text "40,95mil (1,040mm)" at 861.512,303.44 h1.52
  text "PTH" at 877.683,303.44 h1.52
  text "Round" at 884.266,303.44 h1.52
  text "Top Layer - Bottom Layer" at 893.798,303.44 h1.52
  text "1" at 853.076,300.283 h1.52
  text "63,00mil (1,600mm)" at 861.512,300.283 h1.52
  text "PTH" at 877.683,300.283 h1.52
  text "Round" at 884.266,300.283 h1.52
  text "Top Layer - Bottom Layer" at 893.798,300.283 h1.52
  text "8" at 853.076,297.125 h1.52
  text "66,93mil (1,700mm)" at 861.512,297.125 h1.52
  text "PTH" at 877.683,297.125 h1.52
  text "Round" at 884.266,297.125 h1.52
  text "Top Layer - Bottom Layer" at 893.798,297.125 h1.52
  text "+/-3,94mil" at 912.203,297.125 h1.52
  text "G" at 844.8,296.872 h1.4
  text "333 Total" at 853.076,293.968 h1.52
  text ".Layer_Name" at 14.656,-21.806 h1.52
M17 Embedded Cavity:
  text ".Layer_Name" at 14.656,-21.806 h1.52
M18 Embedded Assembly:
  text ".Layer_Name" at 14.656,-21.806 h1.52
M19 Embedded Keepout:
  text ".Layer_Name" at 14.402,-21.806 h1.52

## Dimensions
0,-10.16 to 25.4,-10.16 on M2 Board Dimensions
0,0 to 61,0 on M2 Board Dimensions
0,0 to 0,47.5 on M2 Board Dimensions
